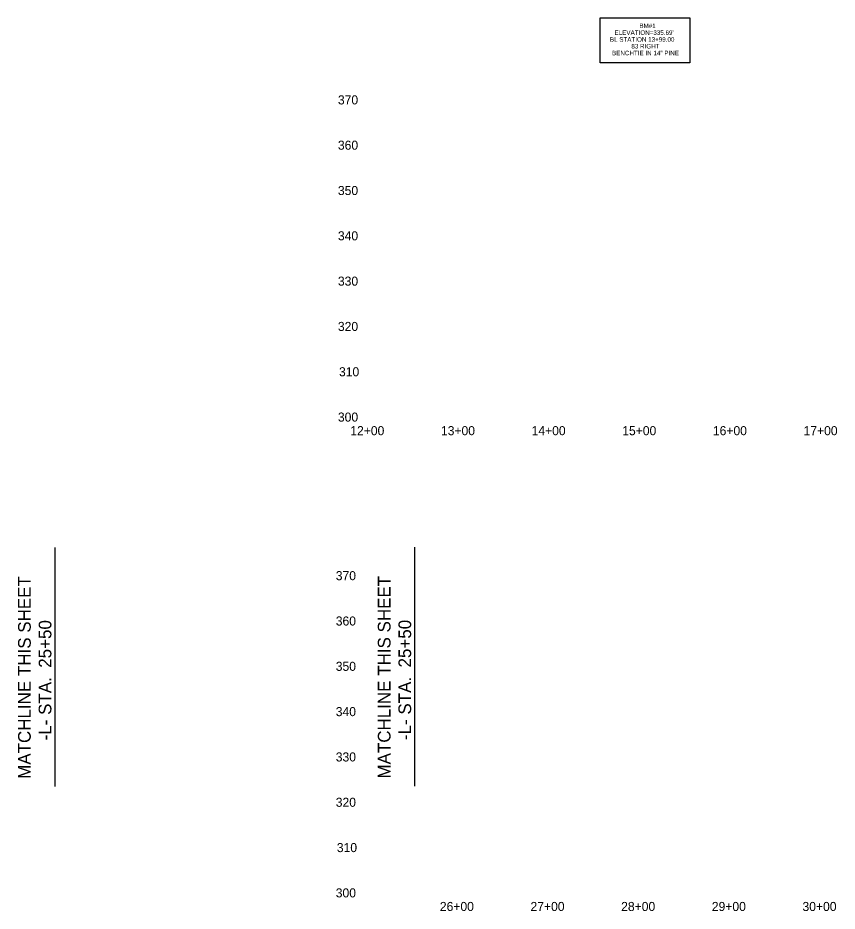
# Model space of a CAD drawing. Extents: x 2044664 to 2046614, y 755540 to 756566.
# Drawn here: x 2044664 to 2045568, y 755540 to 756526 of the extents above; entities that cross this region are included whole.
import ezdxf

# ---------------------------------------------------------------- set-up
doc = ezdxf.new("R2010")
doc.units = 0
for name, color, linetype in [('Exist Vertical Profile Horizontal Axis Label Major', 7, 'Continuous'), ('Exist Vertical Profile Vertical Axis Label', 7, 'Continuous'), ('Matchline', 7, 'Continuous'), ('Matchline Text', 7, 'Continuous'), ('Prop Grid Mask', 7, 'Continuous')]:
    doc.layers.add(name, color=color, linetype=linetype)

msp = doc.modelspace()

# ---------------------------------------------------------------- linework, layer by layer
at = {"layer": 'Matchline'}
for p, q in [((2044704.78, 755941.67), (2044704.78, 755677.72)), ((2045101.63, 755941.99), (2045101.63, 755678.04))]:
    msp.add_line(p, q, dxfattribs=at)
at = {"layer": 'Prop Grid Mask'}
msp.add_lwpolyline([(2045306.27, 756525.9), (2045405.49, 756525.9), (2045405.49, 756476.28), (2045306.27, 756476.28)], close=True, dxfattribs=at)

# ---------------------------------------------------------------- texts
at = {"layer": 'Exist Vertical Profile Horizontal Axis Label Major'}
for s, p in [('12+00', (2045030.76, 756065.41)), ('13+00', (2045130.76, 756065.41)), ('14+00', (2045230.76, 756065.41)), ('15+00', (2045330.76, 756065.41)), ('16+00', (2045430.76, 756065.41)), ('17+00', (2045530.76, 756065.41)), ('26+00', (2045129.57, 755540.41)), ('27+00', (2045229.57, 755540.41)), ('28+00', (2045329.57, 755540.41)), ('29+00', (2045429.57, 755540.41)), ('30+00', (2045529.57, 755540.41))]:
    msp.add_text(s, height=10, dxfattribs=at).set_placement(p)
at = {"layer": 'Exist Vertical Profile Vertical Axis Label'}
for s, p in [('370', (2045017.11, 756430.41)), ('360', (2045017.11, 756380.41)), ('350', (2045017.11, 756330.41)), ('340', (2045017.11, 756280.41)), ('330', (2045017.11, 756230.41)), ('320', (2045017.11, 756180.41)), ('310', (2045018.31, 756130.41)), ('300', (2045017.11, 756080.41)), ('370', (2045014.74, 755905.41)), ('360', (2045014.74, 755855.41)), ('350', (2045014.74, 755805.41)), ('340', (2045014.74, 755755.41)), ('330', (2045014.74, 755705.41)), ('320', (2045014.74, 755655.41)), ('310', (2045015.94, 755605.41)), ('300', (2045014.74, 755555.41))]:
    msp.add_text(s, height=10, dxfattribs=at).set_placement(p)
at = {"layer": 'Matchline Text'}
for s, p in [('MATCHLINE THIS SHEET', (2044678.29, 755686.25)), ('MATCHLINE THIS SHEET', (2045075.15, 755686.57)), ('-L- STA.  25+50', (2044701.04, 755728.7)), ('-L- STA.  25+50', (2045097.9, 755729.02))]:
    msp.add_text(s, height=14, rotation=90, dxfattribs=at).set_placement(p)
at = {"layer": 'Prop Grid Mask'}
for s, p in [('BM#1', (2045349.67, 756514.62)), ('BL STATION 13+99.00', (2045317.15, 756499.62)), ("ELEVATION=335.69'", (2045322.27, 756507.12)), ('83 RIGHT', (2045340.81, 756492.12)), ('BENCHTIE IN 14" PINE', (2045319.49, 756484.62))]:
    msp.add_text(s, height=5, rotation=360, dxfattribs=at).set_placement(p)

doc.saveas('drawing.dxf')
